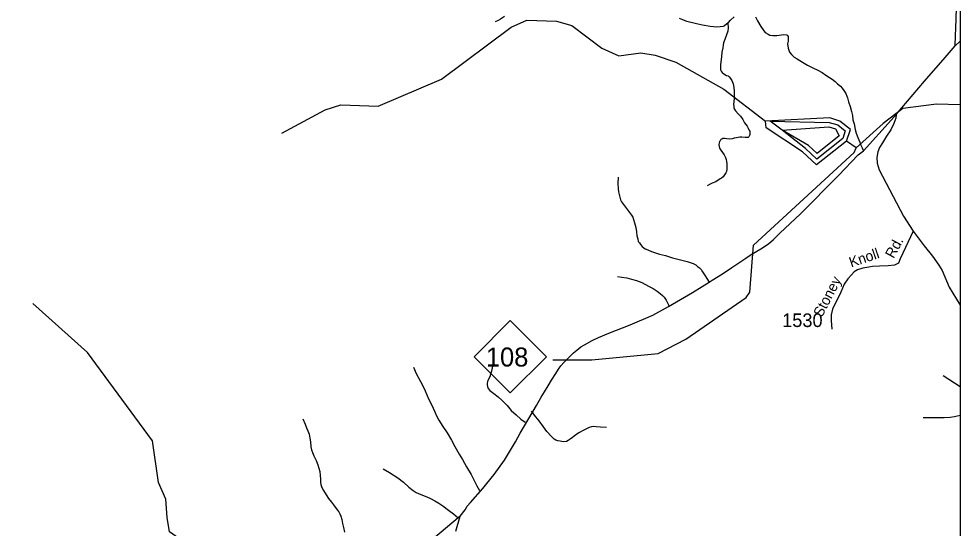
# Model space of a CAD drawing. Extents: x 990631 to 1056237, y 535999 to 585651.
# Drawn here: x 1047577 to 1056237, y 573460 to 578146 of the extents above; entities that cross this region are included whole.
import ezdxf

# ---------------------------------------------------------------- set-up
doc = ezdxf.new("R2010")
doc.units = 0
for name, color, linetype in [('Exist Hydrographic Buffer Line', 7, 'Continuous'), ('Exist Hydrographic Creek Single Shore', 7, 'Continuous'), ('Exist Hydrographic Misc Water Feature', 7, 'Continuous'), ('Exist Hydrographic Pond Over 1500 Sq Ft', 7, 'Continuous'), ('Exist Road Non-System Type 51', 7, 'Continuous'), ('Exist Road Primary NC Attributed', 7, 'Continuous'), ('Exist Road Primary NC Shield CELL', 7, 'Continuous'), ('Exist Road Primary NC Shield Number Label', 7, 'Continuous'), ('Exist Road Secondary Type 51 Attributed', 7, 'Continuous'), ('Exist Road Secondary Type 51 Label', 7, 'Continuous'), ('Exist Road Secondary Type 51 Number Label', 7, 'Continuous'), ('Scratch_Level_3', 7, 'Continuous')]:
    doc.layers.add(name, color=color, linetype=linetype)

msp = doc.modelspace()

# ---------------------------------------------------------------- linework, layer by layer
at = {"layer": 'Exist Hydrographic Buffer Line'}
for points in [[(1054490, 577205.4), (1055033.6, 577193.5), (1055110.7, 577169.6), (1055180.6, 577114.5), (1055156.6, 577044.7), (1054918.7, 576855.8), (1054815, 576953), (1054598.6, 577121), (1054490, 577205.4)], [(1054598.6, 577121), (1055028.5, 577153.1), (1055091.8, 577133.6), (1055122.6, 577068.8), (1054920.9, 576908.6), (1054842.3, 576982.2), (1054598.6, 577121)]]:
    msp.add_lwpolyline(points, dxfattribs=at)
at = {"layer": 'Exist Hydrographic Creek Single Shore'}
for points in [[(1049997.6, 577095.6), (1050396.6, 577307.5), (1050539.6, 577353.9), (1050881.6, 577343.7), (1051464.6, 577591.2), (1052105.6, 578070.7), (1052249.6, 578133.4), (1052524.7, 578124.6), (1052664.6, 578085.7), (1052941.6, 577876.6), (1053097.7, 577804.6), (1053298.6, 577833.3), (1053431.6, 577810.9), (1053621.6, 577748.1), (1054063.7, 577499.6), (1054445.6, 577203.1)], [(1056237.4, 577354.7), (1056018.6, 577361.8), (1055708.6, 577322.1), (1055529.6, 577184.5), (1055280.7, 576959.8)], [(1048941.6, 573559.1), (1048930.6, 573726.7), (1048860.6, 573879.1), (1048806.5, 574264.1), (1048207, 575077.1), (1047704.4, 575527)], [(1056080.6, 574866.1), (1056237.4, 574762.4)], [(1050221.6, 572031.2), (1050034.5, 572273.5), (1049923.6, 572452.9), (1049904.6, 572620.7), (1049959.6, 572787), (1049913.5, 572896.2), (1049808.5, 573016.5), (1049595.6, 573122.5), (1049490.6, 573242.8), (1049317.5, 573305.4), (1049076.6, 573346.3), (1048962.6, 573427.4), (1048941.6, 573559.1)]]:
    msp.add_lwpolyline(points, dxfattribs=at)
at = {"layer": 'Exist Hydrographic Misc Water Feature'}
msp.add_line((1055280.7, 576959.8), (1055190.6, 577020.7), dxfattribs=at)
msp.add_lwpolyline([(1052490.6, 575007.3), (1052849.6, 575009.9), (1053459.6, 575066.6), (1053714.6, 575199.2), (1054268.6, 575582), (1054303.6, 575630.5), (1054334.6, 576063.1), (1055262.6, 576917.5), (1055280.7, 576959.8)], dxfattribs=at)
at = {"layer": 'Exist Hydrographic Pond Over 1500 Sq Ft'}
for points in [[(1055190.6, 577020.7), (1055227.7, 577128.3), (1055129.6, 577205.7), (1055038.6, 577233.8), (1054445.6, 577203.1)], [(1054787.6, 576923.8), (1054452.7, 577143.8), (1054445.6, 577203.1)], [(1055190.6, 577020.7), (1054916.6, 576803), (1054787.6, 576923.8)]]:
    msp.add_lwpolyline(points, dxfattribs=at)
at = {"layer": 'Exist Road Non-System Type 51'}
for points in [[(1052045.7, 578167.3), (1052008.8, 578142.6), (1051986.5, 578129.3), (1051960.1, 578120)], [(1054101.1, 578105.6), (1054088.7, 578095.8), (1054070.3, 578082.4), (1054056.1, 578074.9), (1054029.8, 578071.8), (1053997.8, 578070.8), (1053937.9, 578074.6), (1053866.3, 578087.1), (1053810.7, 578100.8), (1053723.3, 578121.6), (1053685.8, 578136.7), (1053656, 578147.7)], [(1054101.1, 578105.6), (1054107.3, 578111.2), (1054123.9, 578132.7), (1054156.9, 578163.7)], [(1054353, 578163.3), (1054373.9, 578126.7), (1054402.2, 578075.7), (1054431, 578034.9), (1054444.5, 578020.4), (1054470.1, 578005.5), (1054485.9, 577997), (1054513.8, 577994.2), (1054551.8, 577992.9), (1054614, 578001), (1054640, 578000.1), (1054645.9, 577996), (1054655.5, 577983.6), (1054655, 577971.6), (1054654.2, 577941.6), (1054647.3, 577915.7), (1054654.1, 577877.6), (1054659.5, 577857.4), (1054667, 577839.1), (1054686.1, 577816.5), (1054711.5, 577793.6), (1054738.9, 577776.8), (1054786, 577747.3), (1054833.2, 577719.7), (1054882.3, 577694.1), (1054927.7, 577672.6), (1054969.1, 577651.4), (1055002.2, 577628.3), (1055035.6, 577607.2), (1055059.1, 577590.3), (1055088.5, 577569.5), (1055109.9, 577548.7), (1055135, 577526), (1055152.5, 577507.4), (1055167.9, 577486.9), (1055185.1, 577460.3), (1055194.2, 577433.9), (1055199.7, 577419.8), (1055210.6, 577383.4), (1055225.3, 577340.9), (1055237.8, 577292.4), (1055246.6, 577256.2), (1055251.2, 577215.9), (1055262.1, 577179.7), (1055272.5, 577129.3), (1055281.4, 577094.9), (1055296.2, 577054.4), (1055312.8, 577011.8), (1055323.8, 576983.6), (1055335.1, 576959.1), (1055348.2, 576932.7)], [(1054101.1, 578105.6), (1054101.7, 578063.3), (1054098.7, 578033.4), (1054087.6, 577999.8), (1054072.1, 577956.3), (1054061.3, 577926.7), (1054056.5, 577904.8), (1054053.8, 577878.8), (1054044.6, 577839), (1054041.2, 577799.3), (1054032.8, 577723.4), (1054032, 577703.4), (1054031.6, 577689.4), (1054033.3, 577675.4), (1054038.8, 577663.2), (1054048.4, 577650.9), (1054064.2, 577640.3), (1054087.7, 577625.7), (1054103.6, 577621.1), (1054111.2, 577612.8), (1054124.7, 577598.3), (1054136.1, 577577.9), (1054143.7, 577563.7), (1054149.1, 577547.6), (1054156.1, 577515.2), (1054157, 577481.2), (1054158, 577449.2), (1054156.9, 577417.2), (1054155.8, 577381.2), (1054153.2, 577361.2), (1054154.6, 577339.2), (1054156.1, 577325.2), (1054157.7, 577317.1), (1054169.1, 577298.7), (1054194.4, 577272), (1054215.8, 577249.1), (1054236.8, 577218.5), (1054253.7, 577187.9), (1054276.7, 577157.1), (1054286.2, 577140.9), (1054293.7, 577124.5), (1054301.2, 577112.4), (1054302.7, 577096.3), (1054302.4, 577082.3), (1054300, 577072.4), (1054293.6, 577060.5), (1054287.5, 577054.8), (1054281.4, 577052.9), (1054259.4, 577053.6), (1054229.5, 577056.6), (1054209.5, 577057.2), (1054179.4, 577052.2), (1054159.1, 577048.8), (1054139, 577043.6), (1054116.9, 577040.2), (1054090.9, 577041), (1054069, 577043.8), (1054055, 577044.3), (1054044.9, 577038.5), (1054036.6, 577034.9), (1054028.4, 577025), (1054022, 577017.3), (1054019.8, 577005.4), (1054017, 576987.4), (1054020.7, 576971.4), (1054024.2, 576957.1), (1054035.7, 576938.8), (1054050.8, 576916.3), (1054066.2, 576893.8), (1054077.5, 576869.4), (1054084.9, 576851.2), (1054086.1, 576833), (1054091.5, 576810.9), (1054090.8, 576784.9), (1054089.9, 576762.9), (1054087.3, 576742.9), (1054080.9, 576729), (1054068.3, 576709.5), (1054055.7, 576691.9), (1054041.3, 576680.4), (1054029.1, 576672.9), (1053988.2, 576646.1), (1053955.7, 576633.1), (1053931.5, 576621.8), (1053911, 576610.6)], [(1053090.9, 576688.9), (1053089.2, 576630.9), (1053091.5, 576580.7), (1053094.6, 576554.6), (1053099.9, 576528.5), (1053105.1, 576506.4), (1053112.4, 576482), (1053121.8, 576461.6), (1053138.9, 576437.1), (1053167.8, 576402.3), (1053194.6, 576363.3), (1053213.9, 576338.7), (1053225.2, 576320.3), (1053232.5, 576300.1), (1053241.5, 576269.7), (1053252.2, 576225.3), (1053258.8, 576185.2), (1053263.8, 576151), (1053271, 576122.7), (1053276.1, 576096.6), (1053285.6, 576084.2), (1053295.3, 576069.8), (1053310.6, 576051.5), (1053328.3, 576038.7), (1053340, 576030.5), (1053363.8, 576019.6), (1053397.3, 576006.5), (1053472.6, 575982.2), (1053526.2, 575968.5), (1053589.6, 575948.4), (1053663, 575927.9), (1053724.6, 575914.1), (1053754.2, 575905.1), (1053780, 575894.2), (1053805.6, 575883.5), (1053821.1, 575868.9), (1053838.8, 575856.4), (1053854.3, 575839.9), (1053867.5, 575819.4), (1053890.4, 575782.5), (1053905.6, 575756), (1053928.6, 575723.3)], [(1053085.8, 575776.5), (1053123.4, 575769.1), (1053171.3, 575763.6), (1053214.9, 575752.3), (1053258.7, 575738.8), (1053308.1, 575719.2), (1053371.1, 575687.1), (1053412.5, 575665.9), (1053449.6, 575640.7), (1053476.9, 575619.8), (1053498.4, 575601.1), (1053513.9, 575584.6), (1053532.9, 575558), (1053546.2, 575533.5), (1053557.4, 575509.1)], [(1051207.7, 574939.9), (1051231.8, 574883.2), (1051273.5, 574809.7), (1051296, 574763.1), (1051314.8, 574722.5), (1051344.6, 574651.4), (1051372.9, 574598.5), (1051404.8, 574531.4), (1051419.4, 574494.9), (1051440.2, 574452.2), (1051478.5, 574394.9), (1051518.5, 574335.6), (1051556.3, 574268.4), (1051588.6, 574211.4), (1051628.4, 574141.9), (1051658.8, 574092.9), (1051696.7, 574023.7), (1051738.4, 573952.3), (1051766.5, 573897.3), (1051791, 573848.6), (1051813.8, 573807.7)], [(1051934.6, 574950.7), (1051925.1, 574904.9), (1051916.1, 574875.2), (1051909.4, 574851.4), (1051898.6, 574831.8), (1051892.1, 574815.9), (1051889.9, 574807.9), (1051885.4, 574792.2), (1051886.9, 574778.2), (1051888.4, 574764), (1051895.8, 574745.8), (1051909.3, 574727.3), (1051946.3, 574698.2), (1051985.5, 574669), (1052022.5, 574635.6), (1052069, 574590.1), (1052105.4, 574542.9), (1052152.2, 574501.4), (1052195.1, 574464.1), (1052234.1, 574436.7)], [(1052983, 574386.8), (1052927, 574388.5), (1052889.3, 574393.7), (1052865.3, 574394.4), (1052845.2, 574391.2), (1052824.9, 574385.8), (1052792.4, 574370.8), (1052769.9, 574357.5), (1052735.4, 574340.6), (1052702.7, 574317.6), (1052671.8, 574294.6), (1052649.5, 574279.3), (1052631.1, 574267.8), (1052614.7, 574258.4), (1052588.6, 574255.3), (1052556.7, 574260.3), (1052536.8, 574262.9), (1052517.1, 574269.5), (1052501.3, 574280.1), (1052476.1, 574303), (1052433.4, 574348.3), (1052402.9, 574391.3), (1052364.6, 574446.7), (1052333.7, 574483.7), (1052293.4, 574536.9)], [(1055895.8, 574477.3), (1055990, 574478.4), (1056090, 574477.2), (1056144.2, 574481.5), (1056186.3, 574488.1), (1056236.7, 574498.5), (1056237.4, 574498.6)], [(1050189.9, 574466.4), (1050210.2, 574415.6), (1050223.2, 574383.1), (1050234.2, 574354.8), (1050247.2, 574324.4), (1050254.1, 574288), (1050261, 574253.9), (1050261.7, 574209.8), (1050268.8, 574181.5), (1050277.9, 574157.3), (1050291, 574124.8), (1050313.6, 574082.1), (1050328.4, 574041.6), (1050335.4, 574011.3), (1050346.3, 573980.9), (1050349.2, 573944.8), (1050352.1, 573910.7), (1050353.2, 573882.7), (1050354.5, 573860.6), (1050363.6, 573834.2), (1050378.9, 573807.7), (1050403.5, 573767), (1050424.4, 573734.2), (1050453.3, 573699.4), (1050470.6, 573674.8), (1050505.1, 573627.5), (1050520.5, 573609.2), (1050530, 573592.8), (1050539.4, 573570.4), (1050548.3, 573538.2), (1050555.2, 573503.9), (1050564.1, 573465.7), (1050572.6, 573423.3)], [(1050929.5, 574006.3), (1050986.6, 573972.4), (1051063, 573921.8), (1051115.6, 573882.2), (1051164.3, 573836.6), (1051203.3, 573807.4), (1051232.8, 573788.4), (1051274.2, 573769.1), (1051329.6, 573747.2), (1051363.1, 573734.1), (1051404.5, 573712.9), (1051441.7, 573689.7), (1051477, 573664.4), (1051529.8, 573626.7), (1051574.7, 573591.2), (1051617.6, 573555.9)]]:
    msp.add_lwpolyline(points, dxfattribs=at)
at = {"layer": 'Exist Road Primary NC Attributed'}
for points in [[(1056191.4, 577899.2), (1056237.4, 577941.6)], [(1055648.8, 577267.1), (1055909.7, 577572.3), (1056100.2, 577791), (1056191.4, 577899.2)], [(1051636.7, 573570.2), (1051681.9, 573629.9), (1051703, 573661.3), (1051732.1, 573696.3), (1051845.1, 573823.5), (1051881.5, 573869.7), (1051948.8, 573953.8), (1052045.4, 574087), (1052147.7, 574255.3), (1052189.7, 574335.2), (1052339.7, 574587.5), (1052381.6, 574666.2), (1052413.2, 574713.2), (1052446.9, 574770.1), (1052478.8, 574823.1), (1052516.6, 574882), (1052542, 574923.3), (1052563, 574952.5), (1052590.1, 574985.7), (1052625.2, 575018.7), (1052649.9, 575043.8), (1052680.9, 575073), (1052711.8, 575097.9), (1052747.4, 575128.7), (1052781, 575145.5), (1052851.1, 575186.2), (1052909.9, 575215.6), (1053003.8, 575254.9), (1053201.3, 575330.6), (1053408.7, 575420.3), (1053553, 575498.8), (1053775.4, 575628.2), (1053863.2, 575683.4), (1053928.6, 575723.3), (1053957.1, 575740.4), (1054051.2, 575801.5), (1054137, 575858.8), (1054218.9, 575914.2), (1054263.9, 575944.7), (1054315, 575977.1), (1054403.5, 576028.7), (1054474.9, 576076.4), (1054521.2, 576117.1), (1054577.5, 576174.9), (1054674.3, 576263.7), (1054769.3, 576350.9), (1055118.1, 576705.9), (1055300.2, 576895.1), (1055348.2, 576932.7), (1055601.4, 577213.4), (1055648.8, 577267.1)], [(1051596.4, 573432.6), (1051636.7, 573570.2)]]:
    msp.add_lwpolyline(points, dxfattribs=at)
at = {"layer": 'Exist Road Primary NC Shield CELL'}
msp.add_lwpolyline([(1051764.8, 575036.7), (1052097.8, 575369.7), (1052430.8, 575036.7), (1052097.8, 574703.7)], close=True, dxfattribs=at)
at = {"layer": 'Exist Road Secondary Type 51 Attributed'}
for points in [[(1056191.4, 577899.2), (1056194.1, 577991.5), (1056198.7, 578060.5), (1056203.8, 578242.6), (1056197.4, 578373.3), (1056171.8, 578590), (1056165.4, 578673.3), (1056168, 578706.7), (1056188.5, 578729.7)], [(1055648.8, 577267.1), (1055646.3, 577231.6), (1055628.1, 577183.9), (1055598.6, 577125.1), (1055560.8, 577066.2), (1055523, 577005.9), (1055496.3, 576961), (1055479.5, 576921.8), (1055471.1, 576871.3), (1055473.2, 576818.3), (1055492.6, 576756.6), (1055714.6, 576331.7), (1055805.2, 576193.8)], [(1055805.2, 576193.8), (1055686.4, 575938.5), (1055669.3, 575897.6), (1055631.8, 575878.6), (1055575.4, 575875.1), (1055494.4, 575869.8), (1055432.2, 575867.2), (1055395.8, 575860.3), (1055341.1, 575852.2), (1055291.7, 575838.1), (1055261.8, 575816.9), (1055237.1, 575790.4), (1055203.6, 575755.2), (1055170.1, 575704.1), (1055138.4, 575631.8), (1055062.7, 575474.9), (1055050.3, 575423.7), (1055050.3, 575370.8), (1055057.4, 575289.7)], [(1055805.2, 576193.8), (1055906.7, 576058.4), (1055982.4, 575963.2), (1056040.6, 575878.6), (1056070.5, 575829.2), (1056137.5, 575677.6), (1056202.7, 575568.3), (1056237.4, 575511.5)], [(1051636.7, 573570.2), (1051249.3, 573245.4)]]:
    msp.add_lwpolyline(points, dxfattribs=at)
at = {"layer": 'Scratch_Level_3'}
msp.add_lwpolyline([(1056237.4, 535999.3), (990630.7, 535999.3), (990630.7, 585651.1), (1056237.4, 585651.1)], close=True, dxfattribs=at)

# ---------------------------------------------------------------- texts
at = {"layer": 'Exist Road Primary NC Shield Number Label'}
msp.add_text('108', height=175, dxfattribs=at).set_placement((1051873.9, 574947))
at = {"layer": 'Exist Road Secondary Type 51 Label'}
for s, rotation, p in [('Rd.', 61.46404, (1055625.2, 575935.1)), ('Knoll', 18.89736, (1055234.7, 575857.2)), ('Stoney', 62.58489, (1054965, 575393.7))]:
    msp.add_text(s, height=95, rotation=rotation, dxfattribs=at).set_placement(p)
at = {"layer": 'Exist Road Secondary Type 51 Number Label'}
msp.add_text('1530', height=125, dxfattribs=at).set_placement((1054599.6, 575310.6))

doc.saveas('drawing.dxf')
